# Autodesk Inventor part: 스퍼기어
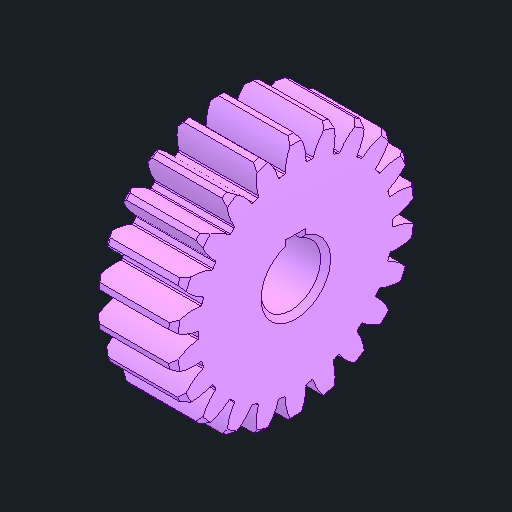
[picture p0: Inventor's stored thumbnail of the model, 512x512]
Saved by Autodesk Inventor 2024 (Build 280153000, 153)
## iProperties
Created: 2025-02
Part Number: 스퍼기어
Material: 강철, 합금
Document SubType Name: Modeling
Designer: kh_501
Density: 7.73 g/cm^3
Appearance: 기본값
Author: jhkim
Sending System: Autodesk Inventor 2025
Preprocessor: ST-DEVELOPER v20
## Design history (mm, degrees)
feature "솔리드1"
node "솔리드2"
